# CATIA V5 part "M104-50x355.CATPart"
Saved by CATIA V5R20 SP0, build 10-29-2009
Part number: M104-50x355
Source: Unknown
Bounding box of the stored display mesh (mm): x -24.865 to 24.865, y -24.997 to 24.997, z 0 to 355
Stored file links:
  C:\Users\Utente\Desktop\IO LAVORO\3D X SITO CF\X SITO\M104\M104-50x355.CATPart
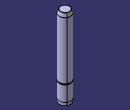
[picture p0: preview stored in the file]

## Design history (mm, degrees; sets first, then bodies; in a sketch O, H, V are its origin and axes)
Body1 (main body)
  Solid1 "PartBody": solid without history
